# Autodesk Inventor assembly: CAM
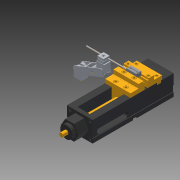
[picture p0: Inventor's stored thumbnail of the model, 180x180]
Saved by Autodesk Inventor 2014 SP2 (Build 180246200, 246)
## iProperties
Created: 2005-05
Part Number: CAM
Document SubType Name: Assembly
Designer: Administrator
Author: Administrator
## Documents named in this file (3)
- C:\SolidCAM_Temp\PRISMA IVCAM ZWISCHENSTAND1\PRISMA IVCAM ZWISCHENSTAND1.IAM
- C:\SolidCAM_Temp\PRISMA IVCAM ZWISCHENSTAND1\DesignModel.iam
- C:\SolidCAM_Temp\PRISMA IVCAM ZWISCHENSTAND1\CAM.IPT
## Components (2 placed, 2 different names)
1. DesignModel:1 [sub-assembly]
2. CAM:1
